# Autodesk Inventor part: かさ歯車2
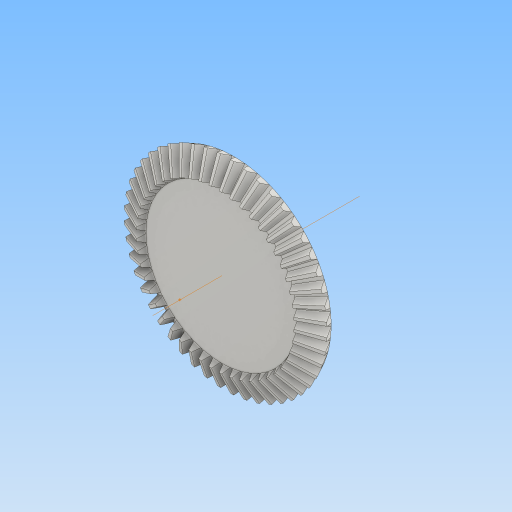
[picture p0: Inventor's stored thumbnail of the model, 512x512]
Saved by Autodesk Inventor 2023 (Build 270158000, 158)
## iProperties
Created: 2024-01
Part Number: かさ歯車2
Material: Steel, Mild
Document SubType Name: Modeling
Designer: kumagai
Categories: <?xml version="1.0" encoding="UTF-16"?> <MemberInstance><Categories><FamilyTemplate><FamilyTemplateParameter ValueType="xs:double" Id="1" ObjectReferenceKey="da
Mass: 60.9118 g
Surface Area: 34.3074 cm^2
Volume: 7.7496 cm^3
Density: 7.86 g/cm^3
Appearance: Steel
CustomPartVersion: 1
Author: kumagai
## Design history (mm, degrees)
node "上側の点"
node "メッシュ平面2"
sketch "歯のボディ スケッチ"
  geometry: L1 (0, 0)-(23.463, -13.073); L2 (23.463, -13.073)-(24.447, -11.106); L3 (24.447, -11.106)-(0, 0); L4 (24, -12)-(0, 0); L5 (18.217, -10.15)-(18.981, -8.622); L6 (23.463, -13.073)-(18.217, -10.15); L7 (24.447, -11.106)-(18.981, -8.622); L8 (0, -39.387)-(0, 6.564) reference; L9 (0, -12)-(24.447, -12)
  constraints: 16 end point, 4 point on line, 3 perpendicular, 2 collinear, 1 horizontal alignment, 1 vertical alignment
  dimensions: "d0" = 48 diameter of L4.start L8 (= da_de); "d1" = 46.92669 diameter of L1.end L8 (= da_dfe); "d2" = 48.89443 diameter of L2.end L8 (= da_dae); "d3" = 6 distance between parallel lines of L2 L5 (= da_b); "d4" = 11.10557 vertical distance of L2.end L1.start (= da_ve)
revolve "歯のボディ" sketch "歯のボディ スケッチ" stored, may be unused: angle "d5" = 90 deg
node "始点"
node "歯の平面"
sketch "開始スケッチ"
  geometry: L1 (0, -23.505)-(0, 10.645) reference; L2 (-0.325, -1.464)-(0.325, -1.464); A1 r 18.703 centre (-18.347, -6.463) between (-0.325, -1.464) and (-1.49, 1.64); A2 r 18.703 centre (18.347, -6.463) between (1.49, 1.64) and (0.325, -1.464); A3 r 55.326 centre (0, -53.666) between (1.49, 1.64) and (-1.49, 1.64); 1 further point
  constraints: 6 point on circle, 3 centre point, 3 symmetric about line, 2 end point, 1 coincident, 1 perpendicular, 1 other
  dimensions: "d7" = 18.70268 radius of A1 (= fd_rr); "d8" = 18.34686 horizontal distance of point (0, -53.666) A1.centre (= fd_x); "d9" = 47.20293 vertical distance of point (0, -53.666) A1.centre (= fd_y); "d57" = 55.32563 radius of A3 (= 0.5 x fd_dva + 0.3 x da_he); "d58" = 52.20163 distance from line of A3.centre L2 (= 0.5 x fd_dva - 1.12 x da_he)
node "終了側の点"
  node "終了平面"
sketch "終了側スケッチ"
  geometry: L1 (0, -15.354)-(0, 6.953) reference; L2 (-0.251, -1.131)-(0.251, -1.131); A1 r 14.444 centre (-14.169, -4.991) between (-0.251, -1.131) and (-1.151, 1.266); A2 r 14.444 centre (14.169, -4.991) between (1.151, 1.266) and (0.251, -1.131); A3 r 42.728 centre (0, -41.446) between (1.151, 1.266) and (-1.151, 1.266); 1 further point
  constraints: 6 point on circle, 3 centre point, 3 symmetric about line, 2 end point, 1 coincident, 1 other
  dimensions: "d12" = 14.44396 radius of A1 (computed from fd_rr, fd_ratio); "d15" = 14.16917 horizontal distance of A1.centre point (0, -41.446) (computed from fd_x, fd_ratio); "d16" = 36.45453 vertical distance of A1.centre point (0, -41.446) (computed from fd_y, fd_ratio); "d59" = 42.72764 radius of A3 (computed from d57, fd_ratio); "d60" = 40.31499 distance from line of A3.centre L2 (computed from d58, fd_ratio)
feature "Loft" sketch "終了側スケッチ" dims "d17" = 0, "d18" = 90 deg, "d19" = 0, "d20" = 90 deg, "d89" = 0, "da_teethtype" = 0 [user parameter]
sketch "3D スケッチ(右)"
  node "Helical Curve Right" dims "d65" = 164.5695 (computed from da_dm, da_delta, da_beta), "d66" = 31.5, "d67" = 48 (= da_de), "d68" = -11.07149 (= -da_delta), "d69" = 2.73248 (computed from fd_loft, da_delta)
node "終了平面(右)"
sketch "終了側スケッチ(右)"
  geometry: L1 (0, -51.343)-(0, 13.664) reference; L2 (-0.251, -1.131)-(0.251, -1.131); A1 r 14.444 centre (-14.169, -4.991) between (-0.251, -1.131) and (-1.151, 1.266); A2 r 14.444 centre (14.169, -4.991) between (1.151, 1.266) and (0.251, -1.131); A3 r 42.728 centre (0, -41.446) between (1.151, 1.266) and (-1.151, 1.266); 1 further point
  constraints: 6 point on circle, 3 centre point, 3 symmetric about line, 2 end point, 1 coincident, 1 perpendicular, 1 other
  dimensions: "d70" = 14.16917 horizontal distance of A3.centre A1.centre (computed from fd_x, fd_ratio); "d71" = 36.45453 vertical distance of point (0, -41.446) A1.centre (computed from fd_y, fd_ratio); "d72" = 14.44396 radius of A1 (computed from fd_rr, fd_ratio); "d73" = 40.31499 distance from line of point (0, -41.446) L2 (computed from d58, fd_ratio); "d74" = 42.72764 radius of A3 (computed from d57, fd_ratio)
feature "ロフト(右)" sketch "終了側スケッチ(右)" dims "d75" = 0, "d77" = 0, "d79" = 0, "d80" = 90 deg, "d85" = 20, "d92" = 90 deg, "d93" = 90 deg, "da_teethtype" = 0 [user parameter]
sketch "3D スケッチ(左)"
  node "Helical Curve Left" dims "d26" = 164.5695 (computed from da_dm, da_delta, da_beta), "d27" = 2.73248 (computed from fd_loft, da_delta), "d28" = 48 (= da_de), "d29" = -11.07149 (= -da_delta)
node "終了平面(左)"
sketch "終了側スケッチ(左)" dims "d56" = 8.50902 (derived)
  geometry: L1 (0, -52.204)-(0, 14.553) reference; L2 (-0.251, -1.105)-(0.251, -1.105); A1 r 14.444 centre (-14.169, -4.966) between (-0.251, -1.105) and (-1.151, 1.292); A2 r 14.444 centre (14.169, -4.966) between (1.151, 1.292) and (0.251, -1.105); A3 r 42.728 centre (0, -41.42) between (1.151, 1.292) and (-1.151, 1.292); 2 further points; 1 other entity
  constraints: 6 point on circle, 3 centre point, 3 symmetric about line, 2 end point, 1 coincident, 2 other
  dimensions: "d30" = 14.44396 radius of A1 (computed from fd_rr, fd_ratio); "d31" = 14.16917 horizontal distance of point (0, -41.42) A1.centre (computed from fd_x, fd_ratio); "d32" = 36.45453 vertical distance of A1.centre point (0, -41.42) (computed from fd_y, fd_ratio); "d61" = 42.72764 radius of A3 (computed from d57, fd_ratio); "d62" = 40.31499 distance from line of point (0, -41.42) L2 (computed from d58, fd_ratio)
feature "ロフト(左)" sketch "終了側スケッチ(左)" dims "d35" = 0, "d37" = 0, "d39" = 0, "d40" = 90 deg, "d84" = 10, "d90" = 90 deg, "d91" = 90 deg, "da_teethtype" = 0 [user parameter]
sketch "ボディ スケッチ"
  geometry: L1 (0, -35.038)-(0, -19.531) reference; L2 (23.463, -13.073)-(18.217, -10.15) reference; L3 (18.217, -10.15)-(0, -10.15); L4 (23.463, -13.073)-(0, -13.073)
  constraints: 4 end point, 2 perpendicular, 2 point on line
revolve "固定ボディ" sketch "ボディ スケッチ" stored, may be unused: angle "d46" = 90 deg
sketch "Sketch6"
  geometry: L1 (24, -12)-(0, 0) reference; L2 (0, -37.8)-(0, 6.3) reference
feature "ピッチ円直径" sketch "Sketch6" dims angle "d47" = 90 deg
body "Solid1"
pattern_circular "Circular Pattern" dims angle "d22" = 360 deg, "d88" = 0, "da_teethtype" = 0 [user parameter]
pattern_circular "放射状パターン(右)" dims angle "d82" = 360 deg, "da_teethtype" = 0 [user parameter]
pattern_circular "放射状パターン(左)" dims angle "d42" = 360 deg, "da_teethtype" = 0 [user parameter]
body "Srf1"
other parameters: "da_b" = 6 [user parameter; used in 2 equation terms], "da_de" = 48 [user parameter; used in 4 equation terms], "da_dae" = 48.89443 [user parameter; used in 2 equation terms], "da_dfe" = 46.92669 [user parameter; used in 1 equation term], "da_le" = 26.83282 [user parameter; used in 1 equation term], "da_omega" = 90 deg [user parameter; used in 1 equation term], "da_beta" = 0 [user parameter; used in 2 equation terms], "da_delta" = 11.07149 [user parameter; used in 8 equation terms], "da_alpha" = 20 deg [user parameter; used in 2 equation terms], "da_he" = 2.2 [user parameter; used in 4 equation terms], "da_ve" = 11.10557 [user parameter; used in 1 equation term], "fd_dv" = 107.33126 (computed from da_de, da_delta) [user parameter; used in 1 equation term], "fd_dva" = 109.33126 (computed from da_dae, da_delta) [user parameter; used in 3 equation terms], "fd_dvb" = 100.8584 (computed from fd_dv, da_alpha) [user parameter; used in 2 equation terms], "da_zv" = 1073.31263 [user parameter; used in 1 equation term], "fd_loft" = 6.11 (= da_b + 0.05 x da_he) [user parameter; used in 4 equation terms], "fd_ratio" = 7.72294 (computed from da_le, fd_loft) [user parameter; used in 15 equation terms], "fd_rr" = 18.70268 (computed from fd_dd, fd_dvb) [user parameter; used in 6 equation terms], "fd_angle" = 0.14798 (computed from da_zv) [user parameter; used in 4 equation terms], "fd_x1" = 0.7941 (computed from da_dvw, fd_angle) [user parameter; used in 1 equation term], "fd_y1" = 53.65976 (computed from da_dvw, fd_angle) [user parameter; used in 1 equation term], "fd_x2" = 17.55277 (computed from fd_rr, fd_angle2, fd_angle) [user parameter; used in 1 equation term], "fd_y2" = 6.45682 (computed from fd_rr, fd_angle2, fd_angle) [user parameter; used in 1 equation term], "fd_x" = 18.34686 (= fd_x1 + fd_x2) [user parameter; used in 4 equation terms], "fd_y" = 47.20293 (= fd_y1 - fd_y2) [user parameter; used in 4 equation terms], "fd_angle2" = 3.37692 (computed from fd_dvb, fd_dd, da_alpha) [user parameter; used in 2 equation terms], "fd_dd" = 107.57126 (= fd_dva - 0.8 x da_he) [user parameter; used in 2 equation terms], "da_dvw" = 107.33126 [user parameter; used in 2 equation terms], "d11" = 6.11 (= fd_loft), "da_dm" = 42.63344 [user parameter; used in 2 equation terms], "da_x" = 0 [user parameter], "da_m" = 1 [user parameter], "d48" = 0, "d49" = 0, "d50" = 90 deg (= da_omega), "d51" = 0.6545 (computed from da_z), "d52" = 0, "d53" = 0, "d54" = 0
